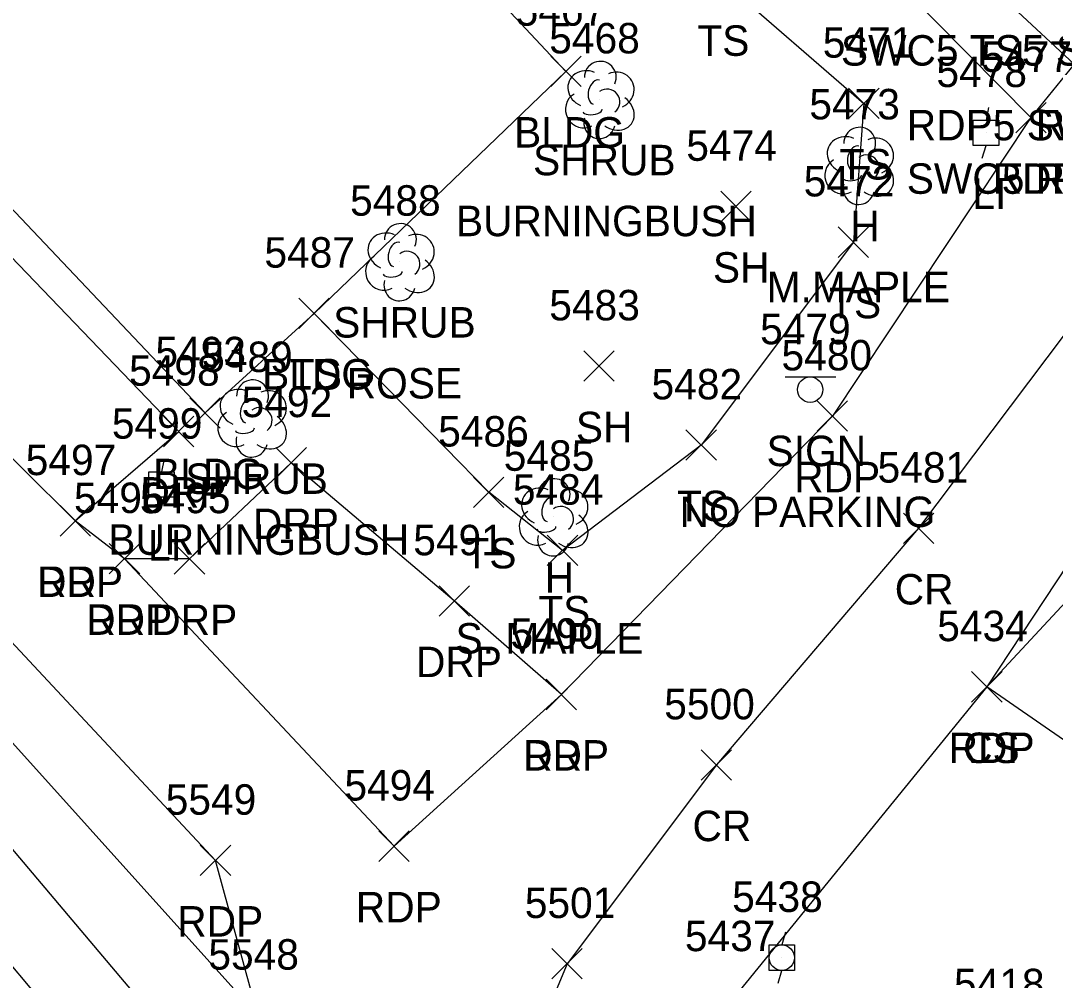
# Model space of a CAD drawing. Extents: x 1618146 to 1620418, y 640749 to 641927.
# Drawn here: x 1620177.9 to 1620245.8, y 641136.7 to 641199.7 of the extents above; entities that cross this region are included whole.
import ezdxf

# ---------------------------------------------------------------- set-up
doc = ezdxf.new("R2010")
doc.units = 0
for name, color, linetype in [('L_A', 7, 'Continuous'), ('L_C', 7, 'Continuous'), ('L_I', 7, 'Continuous'), ('L_TIC', 7, 'Continuous'), ('LBC', 7, 'Continuous'), ('LELB', 7, 'Continuous'), ('LSH', 7, 'Continuous'), ('LTD', 7, 'Continuous'), ('P_A', 7, 'Continuous'), ('P_I', 7, 'Continuous'), ('P_TIC', 7, 'Continuous'), ('PET', 7, 'Continuous'), ('PRC', 7, 'Continuous'), ('R_A', 7, 'Continuous'), ('R_I', 7, 'Continuous'), ('R_TIC', 7, 'Continuous'), ('RDP', 7, 'Continuous'), ('RR', 7, 'Continuous'), ('RRB', 7, 'Continuous'), ('RSW', 7, 'Continuous'), ('S_A', 7, 'Continuous'), ('S_C', 7, 'Continuous'), ('S_I', 7, 'Continuous'), ('SSGN', 7, 'Continuous'), ('U_A', 7, 'Continuous'), ('U_I', 7, 'Continuous'), ('ULP', 7, 'Continuous'), ('UP', 7, 'Continuous')]:
    doc.layers.add(name, color=color, linetype=linetype)

msp = doc.modelspace()

# ---------------------------------------------------------------- linework, layer by layer
at = {"layer": 'L_TIC'}
for points in [[(1620212.685, 641195.392), (1620214.685, 641197.392)], [(1620214.685, 641195.392), (1620212.685, 641197.392)], [(1620232.244, 641193.294), (1620234.244, 641195.294)], [(1620234.244, 641193.294), (1620232.244, 641195.294)], [(1620223.848, 641186.523), (1620225.848, 641188.523)], [(1620225.848, 641186.523), (1620223.848, 641188.523)], [(1620231.558, 641184.185), (1620233.558, 641186.185)], [(1620233.558, 641184.185), (1620231.558, 641186.185)], [(1620196.139, 641179.509), (1620198.139, 641181.509)], [(1620198.139, 641179.509), (1620196.139, 641181.509)], [(1620196.139, 641179.509), (1620198.139, 641181.509)], [(1620198.139, 641179.509), (1620196.139, 641181.509)], [(1620214.849, 641176.047), (1620216.849, 641178.047)], [(1620216.849, 641176.047), (1620214.849, 641178.047)], [(1620188.981, 641172.967), (1620190.981, 641174.967)], [(1620190.981, 641172.967), (1620188.981, 641174.967)], [(1620221.564, 641170.861), (1620223.564, 641172.861)], [(1620223.564, 641170.861), (1620221.564, 641172.861)], [(1620207.609, 641167.764), (1620209.609, 641169.764)], [(1620209.609, 641167.764), (1620207.609, 641169.764)], [(1620212.458, 641163.948), (1620214.458, 641165.948)], [(1620214.458, 641163.948), (1620212.458, 641165.948)], [(1620240.328, 641154.987), (1620242.328, 641156.987)], [(1620242.328, 641154.987), (1620240.328, 641156.987)], [(1620240.328, 641154.987), (1620242.328, 641156.987)], [(1620242.328, 641154.987), (1620240.328, 641156.987)]]:
    msp.add_lwpolyline(points, dxfattribs=at)
at = {"layer": 'LBC'}
msp.add_lwpolyline([(1620215.058, 641244.302), (1620205.976, 641235.712), (1620202.677, 641232.585), (1620189.499, 641220.107), (1620199.083, 641211.828), (1620201.415, 641213.808), (1620202.472, 641212.521), (1620205.827, 641209.331), (1620206.941, 641208.229), (1620204.756, 641205.896), (1620213.685, 641196.392), (1620197.139, 641180.509), (1620189.981, 641173.967), (1620166.556, 641198.685), (1620162.715, 641202.828), (1620152.839, 641213.225), (1620141.669, 641224.901), (1620165.022, 641247.378), (1620169.209, 641243.063), (1620193.587, 641266.433)], dxfattribs=at)
at = {"layer": 'LELB'}
for points in [[(1620211.815, 641214.968), (1620223.903, 641202.414), (1620233.244, 641194.294), (1620232.558, 641185.185), (1620222.564, 641171.861), (1620213.458, 641164.948), (1620208.609, 641168.764), (1620197.139, 641180.509)], [(1620322.254, 641104.578), (1620328.726, 641115.395), (1620332.253, 641122.244), (1620297.17, 641147.26), (1620261.974, 641167.003), (1620254.964, 641172.982), (1620251.385, 641166.829), (1620241.328, 641155.987)], [(1620310.491, 641089.313), (1620322.254, 641104.578), (1620287.408, 641125.429), (1620251.671, 641148.83), (1620241.328, 641155.987)]]:
    msp.add_lwpolyline(points, dxfattribs=at)
at = {"layer": 'LSH'}
for p, q in [((1620215.893, 641194.573), (1620215.893, 641194.573)), ((1620215.893, 641194.573), (1620215.893, 641194.573)), ((1620202.766, 641183.919), (1620202.766, 641183.919)), ((1620202.766, 641183.919), (1620202.766, 641183.919)), ((1620193.057, 641173.656), (1620193.057, 641173.656)), ((1620193.057, 641173.656), (1620193.057, 641173.656))]:
    msp.add_line(p, q, dxfattribs=at)
for centre in [(1620215.94, 641196.007), (1620202.813, 641185.353), (1620193.104, 641175.09)]:
    msp.add_arc(centre, 1.047, 335.52715, 180.95627, dxfattribs=at)
for centre, major_axis, ratio, start_param, end_param in [((1620215.101, 641195.24), (1.21, -0.512), 0.895232, 1.570796, 4.712389), ((1620216.935, 641195.157), (-1.141, -0.483), 0.949671, 1.570796, 4.712389), ((1620215.685, 641195.032), (-0.208, -0.792), 0.645439, 3.141593, 6.283185), ((1620216.393, 641194.407), (-0.5, 0.667), 0.989748, 3.141593, 6.283185), ((1620214.81, 641193.865), (0.584, -1.042), 0.959034, 3.141593, 6.283185), ((1620216.893, 641193.74), (-1.09, 0.792), 0.841452, 1.570796, 4.712389), ((1620215.435, 641193.823), (-0.625, -0.083), 0.423636, 0, 3.141593), ((1620215.893, 641193.073), (0.265, 1.061), 0.942809, 1.570796, 4.712389), ((1620201.974, 641184.586), (1.21, -0.512), 0.895232, 1.570796, 4.712389), ((1620203.807, 641184.503), (-1.141, -0.483), 0.949671, 1.570796, 4.712389), ((1620202.557, 641184.377), (-0.208, -0.792), 0.645439, 3.141593, 6.283185), ((1620201.683, 641183.211), (0.584, -1.042), 0.959034, 3.141593, 6.283185), ((1620203.266, 641183.752), (-0.5, 0.667), 0.989748, 3.141593, 6.283185), ((1620203.766, 641183.086), (-1.09, 0.792), 0.841452, 1.570796, 4.712389), ((1620202.308, 641183.169), (-0.625, -0.083), 0.423636, 0, 3.141593), ((1620202.766, 641182.419), (0.265, 1.061), 0.942809, 1.570796, 4.712389), ((1620192.265, 641174.323), (1.21, -0.512), 0.895232, 1.570796, 4.712389), ((1620194.098, 641174.24), (-1.141, -0.483), 0.949671, 1.570796, 4.712389), ((1620192.848, 641174.114), (-0.208, -0.792), 0.645439, 3.141593, 6.283185), ((1620193.557, 641173.489), (-0.5, 0.667), 0.989748, 3.141593, 6.283185), ((1620191.974, 641172.947), (0.584, -1.042), 0.959034, 3.141593, 6.283185), ((1620194.057, 641172.823), (-1.09, 0.792), 0.841452, 1.570796, 4.712389), ((1620192.599, 641172.906), (-0.625, -0.083), 0.423636, 0, 3.141593), ((1620193.057, 641172.156), (0.265, 1.061), 0.942809, 1.570796, 4.712389)]:
    msp.add_ellipse(centre, major_axis=major_axis, ratio=ratio, start_param=start_param, end_param=end_param, dxfattribs=at)
at = {"layer": 'LTD'}
for p, q in [((1620232.926, 641190.242), (1620232.926, 641190.242)), ((1620232.926, 641190.242), (1620232.926, 641190.242)), ((1620212.857, 641167.173), (1620212.857, 641167.173)), ((1620212.857, 641167.173), (1620212.857, 641167.173))]:
    msp.add_line(p, q, dxfattribs=at)
for centre in [(1620232.973, 641191.676), (1620212.904, 641168.607)]:
    msp.add_arc(centre, 1.047, 335.52715, 180.95627, dxfattribs=at)
for centre, major_axis, ratio, start_param, end_param in [((1620232.135, 641190.909), (1.21, -0.512), 0.895232, 1.570796, 4.712389), ((1620233.968, 641190.826), (-1.141, -0.483), 0.949671, 1.570796, 4.712389), ((1620232.718, 641190.7), (-0.208, -0.792), 0.645439, 3.141593, 6.283185), ((1620231.843, 641189.534), (0.584, -1.042), 0.959034, 3.141593, 6.283185), ((1620233.426, 641190.076), (-0.5, 0.667), 0.989748, 3.141593, 6.283185), ((1620233.927, 641189.409), (-1.09, 0.792), 0.841452, 1.570796, 4.712389), ((1620232.468, 641189.492), (-0.625, -0.083), 0.423636, 0, 3.141593), ((1620232.927, 641188.742), (0.265, 1.061), 0.942809, 1.570796, 4.712389), ((1620212.065, 641167.839), (1.21, -0.512), 0.895232, 1.570796, 4.712389), ((1620213.899, 641167.756), (-1.141, -0.483), 0.949671, 1.570796, 4.712389), ((1620212.649, 641167.631), (-0.208, -0.792), 0.645439, 3.141593, 6.283185), ((1620213.357, 641167.006), (-0.5, 0.667), 0.989748, 3.141593, 6.283185), ((1620211.774, 641166.464), (0.584, -1.042), 0.959034, 3.141593, 6.283185), ((1620213.857, 641166.34), (-1.09, 0.792), 0.841452, 1.570796, 4.712389), ((1620212.857, 641165.673), (0.265, 1.061), 0.942809, 1.570796, 4.712389), ((1620212.399, 641166.423), (-0.625, -0.083), 0.423636, 0, 3.141593)]:
    msp.add_ellipse(centre, major_axis=major_axis, ratio=ratio, start_param=start_param, end_param=end_param, dxfattribs=at)
at = {"layer": 'P_TIC'}
for points in [[(1620243.221, 641192.357), (1620245.221, 641194.357)], [(1620245.221, 641192.357), (1620243.221, 641194.357)], [(1620230.184, 641172.763), (1620232.184, 641174.763)], [(1620232.184, 641172.763), (1620230.184, 641174.763)], [(1620180.462, 641165.888), (1620182.462, 641167.888)], [(1620182.462, 641165.888), (1620180.462, 641167.888)], [(1620235.843, 641165.396), (1620237.843, 641167.396)], [(1620237.843, 641165.396), (1620235.843, 641167.396)], [(1620183.689, 641163.4), (1620185.689, 641165.4)], [(1620185.689, 641163.4), (1620183.689, 641165.4)], [(1620212.381, 641154.488), (1620214.381, 641156.488)], [(1620214.381, 641154.488), (1620212.381, 641156.488)], [(1620240.328, 641154.987), (1620242.328, 641156.987)], [(1620242.328, 641154.987), (1620240.328, 641156.987)], [(1620222.563, 641149.858), (1620224.563, 641151.858)], [(1620224.563, 641149.858), (1620222.563, 641151.858)], [(1620201.395, 641144.525), (1620203.395, 641146.525)], [(1620203.395, 641144.525), (1620201.395, 641146.525)], [(1620189.666, 641143.593), (1620191.666, 641145.593)], [(1620191.666, 641143.593), (1620189.666, 641145.593)], [(1620212.753, 641136.811), (1620214.753, 641138.811)], [(1620214.753, 641136.811), (1620212.753, 641138.811)]]:
    msp.add_lwpolyline(points, dxfattribs=at)
at = {"layer": 'PET'}
for points in [[(1620248.37, 641210.419), (1620247.05, 641196.867), (1620244.221, 641193.357), (1620231.184, 641173.763), (1620213.381, 641155.488), (1620202.395, 641145.525), (1620184.689, 641164.4), (1620181.462, 641166.888), (1620163.819, 641184.387), (1620152.297, 641193.8)], [(1620264.261, 641193.837), (1620257.522, 641181.671), (1620253.5, 641174.421), (1620241.328, 641155.987), (1620224.756, 641135.636), (1620223.78, 641130.066), (1620229.044, 641107.516), (1620237.42, 641090.889)], [(1620199.84, 641100.892), (1620190.476, 641119.747), (1620190.752, 641121.585), (1620192.149, 641127.788), (1620193.459, 641134.423), (1620190.666, 641144.593), (1620174.447, 641161.945), (1620160.08, 641178.417), (1620147.247, 641189.39)]]:
    msp.add_lwpolyline(points, dxfattribs=at)
at = {"layer": 'PRC'}
msp.add_lwpolyline([(1620256.843, 641199.417), (1620250.092, 641183.972), (1620236.843, 641166.396), (1620223.563, 641150.858), (1620213.753, 641137.811), (1620205.802, 641118.707)], dxfattribs=at)
at = {"layer": 'R_TIC'}
for points in [[(1620243.221, 641192.357), (1620245.221, 641194.357)], [(1620245.221, 641192.357), (1620243.221, 641194.357)], [(1620187.251, 641171.756), (1620189.251, 641173.756)], [(1620189.251, 641171.756), (1620187.251, 641173.756)], [(1620194.641, 641169.695), (1620196.641, 641171.695)], [(1620196.641, 641169.695), (1620194.641, 641171.695)], [(1620180.462, 641165.888), (1620182.462, 641167.888)], [(1620182.462, 641165.888), (1620180.462, 641167.888)], [(1620183.689, 641163.4), (1620185.689, 641165.4)], [(1620185.689, 641163.4), (1620183.689, 641165.4)], [(1620187.963, 641163.388), (1620189.963, 641165.388)], [(1620189.963, 641163.388), (1620187.963, 641165.388)], [(1620205.348, 641160.625), (1620207.348, 641162.625)], [(1620207.348, 641160.625), (1620205.348, 641162.625)], [(1620212.381, 641154.488), (1620214.381, 641156.488)], [(1620214.381, 641154.488), (1620212.381, 641156.488)]]:
    msp.add_lwpolyline(points, dxfattribs=at)
at = {"layer": 'RDP'}
for points in [[(1620181.462, 641166.888), (1620188.251, 641172.756), (1620165.106, 641196.848), (1620161.474, 641200.94), (1620159.631, 641200.696)], [(1620213.381, 641155.488), (1620206.348, 641161.625), (1620195.641, 641170.695), (1620188.963, 641164.388), (1620184.689, 641164.4)]]:
    msp.add_lwpolyline(points, dxfattribs=at)
at = {"layer": 'RR'}
for points in [[(1620192.149, 641127.788), (1620168.312, 641155.994), (1620153.359, 641171.838), (1620133.437, 641191.994), (1620110.111, 641213.081), (1620101.472, 641220.641), (1620055.356, 641258.678), (1620021.942, 641286.099), (1619984.199, 641317.184), (1619946.809, 641347.804), (1619927.299, 641363.881), (1619890.892, 641393.618), (1619862.546, 641416.891)], [(1620190.752, 641121.585), (1620164.758, 641152.663), (1620149.827, 641168.387), (1620129.761, 641188.505), (1620106.878, 641209.401), (1620098.404, 641216.876), (1620053.4, 641253.963), (1620018.83, 641282.236), (1619980.557, 641313.635), (1619944.224, 641343.671), (1619924.209, 641360.052), (1619888.22, 641389.605), (1619859.159, 641413.425)]]:
    msp.add_lwpolyline(points, dxfattribs=at)
at = {"layer": 'RRB'}
msp.add_lwpolyline([(1620282.833, 641005.905), (1620262.956, 641036.105), (1620245.554, 641062.879), (1620222.8, 641095.958), (1620205.802, 641118.707), (1620193.459, 641134.423), (1620171.398, 641158.878), (1620156.473, 641175.88), (1620136.028, 641194.899), (1620112.946, 641215.974), (1620104.578, 641223.126), (1620095.968, 641212.166)], dxfattribs=at)
at = {"layer": 'RSW'}
for points in [[(1620247.05, 641196.867), (1620241.813, 641201.772), (1620221.011, 641223.739), (1620217.686, 641227.233), (1620214.968, 641229.37), (1620205.976, 641235.712)], [(1620202.677, 641232.585), (1620214.484, 641224.007), (1620217.542, 641220.644), (1620231.667, 641206.068), (1620244.221, 641193.357)]]:
    msp.add_lwpolyline(points, dxfattribs=at)
at = {"layer": 'SSGN'}
for p, q in [((1620228.075, 641176.332), (1620231.408, 641176.332)), ((1620229.722, 641175.499), (1620229.722, 641175.499))]:
    msp.add_line(p, q, dxfattribs=at)
msp.add_circle((1620229.722, 641175.499), 0.833, dxfattribs=at)
at = {"layer": 'ULP'}
for p, q in [((1620241.438, 641194.03), (1620241.272, 641193.197)), ((1620240.438, 641191.53), (1620240.438, 641193.197)), ((1620240.438, 641193.197), (1620242.105, 641193.197)), ((1620242.105, 641193.197), (1620242.105, 641191.53)), ((1620241.272, 641192.364), (1620241.272, 641192.364)), ((1620242.105, 641191.53), (1620240.438, 641191.53)), ((1620241.022, 641190.697), (1620241.272, 641191.53)), ((1620187.298, 641170.948), (1620187.131, 641170.114)), ((1620186.298, 641168.448), (1620186.298, 641170.114)), ((1620186.298, 641170.114), (1620187.964, 641170.114)), ((1620187.964, 641170.114), (1620187.964, 641168.448)), ((1620187.131, 641169.281), (1620187.131, 641169.281)), ((1620187.964, 641168.448), (1620186.298, 641168.448)), ((1620186.881, 641167.614), (1620187.131, 641168.448))]:
    msp.add_line(p, q, dxfattribs=at)
at = {"layer": 'UP'}
for p, q in [((1620228.11, 641139.876), (1620227.86, 641139.043)), ((1620227.027, 641137.376), (1620227.027, 641139.043)), ((1620227.027, 641139.043), (1620228.693, 641139.043)), ((1620228.693, 641139.043), (1620228.693, 641137.376)), ((1620227.86, 641138.21), (1620227.86, 641138.21)), ((1620228.693, 641137.376), (1620227.027, 641137.376)), ((1620227.61, 641136.543), (1620227.86, 641137.376))]:
    msp.add_line(p, q, dxfattribs=at)
msp.add_circle((1620227.86, 641138.21), 0.833, dxfattribs=at)

# ---------------------------------------------------------------- texts
at = {"layer": 'L_A'}
for s, p in [('TS', (1620222.313, 641197.414)), ('TS', (1620240.222, 641196.772)), ('BLDG', (1620210.276, 641191.392)), ('SHRUB', (1620211.523, 641189.573)), ('TS', (1620231.654, 641189.294)), ('H', (1620232.359, 641185.242)), ('SH', (1620223.336, 641182.523)), ('TS', (1620230.968, 641180.185)), ('SHRUB', (1620198.396, 641178.919)), ('BLDG', (1620193.73, 641175.509)), ('TS', (1620195.549, 641175.509)), ('SH', (1620214.337, 641172.047)), ('BLDG', (1620186.572, 641168.967)), ('SHRUB', (1620188.687, 641168.656)), ('TS', (1620220.974, 641166.861)), ('TS', (1620207.018, 641163.764)), ('H', (1620212.29, 641162.173)), ('TS', (1620211.868, 641159.948)), ('CS', (1620239.769, 641150.987)), ('CS', (1620239.769, 641150.987))]:
    msp.add_text(s, height=2, dxfattribs=at).set_placement(p)
at = {"layer": 'L_C'}
for s, p in [('BURNINGBUSH', (1620206.46, 641185.573)), ('M.MAPLE', (1620226.864, 641181.242)), ('ROSE', (1620199.286, 641174.919)), ('BURNINGBUSH', (1620183.624, 641164.656)), ('S. MAPLE', (1620206.432, 641158.173))]:
    msp.add_text(s, height=2, dxfattribs=at).set_placement(p)
at = {"layer": 'L_I'}
for s, p in [('5467', (1620210.378, 641199.392)), ('5468', (1620212.586, 641197.573)), ('5471', (1620230.551, 641197.294)), ('5473', (1620229.667, 641193.242)), ('5474', (1620221.588, 641190.523)), ('5472', (1620229.298, 641188.185)), ('5488', (1620199.506, 641186.919)), ('5487', (1620193.879, 641183.509)), ('5487', (1620193.879, 641183.509)), ('5483', (1620212.589, 641180.047)), ('5493', (1620186.722, 641176.967)), ('5489', (1620189.789, 641176.656)), ('5482', (1620219.304, 641174.861)), ('5486', (1620205.294, 641171.764)), ('5485', (1620209.597, 641170.173)), ('5484', (1620210.198, 641167.948)), ('5434', (1620238.068, 641158.987)), ('5434', (1620238.068, 641158.987)), ('5437', (1620221.496, 641138.636)), ('5418', (1620239.167, 641135.48))]:
    msp.add_text(s, height=2, dxfattribs=at).set_placement(p)
at = {"layer": 'P_A'}
for s, p in [('RDP', (1620244.538, 641191.867)), ('RDP', (1620241.709, 641188.357)), ('RDP', (1620228.672, 641168.763)), ('RDP', (1620178.95, 641161.888)), ('CR', (1620235.276, 641161.396)), ('RDP', (1620182.178, 641159.4)), ('RDP', (1620210.869, 641150.488)), ('RDP', (1620238.816, 641150.987)), ('CR', (1620221.996, 641145.858)), ('RDP', (1620199.883, 641140.525)), ('RDP', (1620188.154, 641139.593))]:
    msp.add_text(s, height=2, dxfattribs=at).set_placement(p)
at = {"layer": 'P_I'}
for s, p in [('5477', (1620240.962, 641196.357)), ('5480', (1620227.838, 641176.763)), ('5497', (1620178.202, 641169.888)), ('5481', (1620234.15, 641169.396)), ('5496', (1620181.374, 641167.4)), ('5490', (1620210.035, 641158.488)), ('5434', (1620238.068, 641158.987)), ('5500', (1620220.138, 641153.858)), ('5494', (1620199.135, 641148.525)), ('5549', (1620187.398, 641147.593)), ('5501', (1620210.981, 641140.811)), ('5437', (1620221.496, 641138.636)), ('5548', (1620190.199, 641137.423))]:
    msp.add_text(s, height=2, dxfattribs=at).set_placement(p)
at = {"layer": 'R_A'}
for s, p in [('SWC5 TS5 ST', (1620231.742, 641196.772)), ('RDP5 SWC5 ST', (1620236.066, 641191.867)), ('SWC5 RDP5', (1620236.064, 641188.357)), ('DRP', (1620185.74, 641167.756)), ('DRP', (1620193.13, 641165.695)), ('DRP', (1620178.95, 641161.888)), ('DRP', (1620182.178, 641159.4)), ('DRP', (1620186.451, 641159.388)), ('DRP', (1620203.837, 641156.625)), ('DRP', (1620210.869, 641150.488))]:
    msp.add_text(s, height=2, dxfattribs=at).set_placement(p)
at = {"layer": 'R_I'}
for s, p in [('5477', (1620240.962, 641196.357)), ('5498', (1620184.992, 641175.756)), ('5492', (1620192.382, 641173.695)), ('5497', (1620178.202, 641169.888)), ('5496', (1620181.374, 641167.4)), ('5495', (1620185.703, 641167.388)), ('5491', (1620203.656, 641164.625)), ('5490', (1620210.035, 641158.488)), ('5548', (1620190.199, 641137.423))]:
    msp.add_text(s, height=2, dxfattribs=at).set_placement(p)
at = {"layer": 'S_A'}
msp.add_text('SIGN', height=2, dxfattribs=at).set_placement((1620226.86, 641170.478))
at = {"layer": 'S_C'}
msp.add_text('NO PARKING', height=2, dxfattribs=at).set_placement((1620221.143, 641166.478))
at = {"layer": 'S_I'}
msp.add_text('5479', height=2, dxfattribs=at).set_placement((1620226.434, 641178.478))
at = {"layer": 'U_A'}
for p in [(1620240.374, 641187.364), (1620186.233, 641164.281)]:
    msp.add_text('LI', height=2, dxfattribs=at).set_placement(p)
at = {"layer": 'U_I'}
for s, p in [('5478', (1620238.012, 641195.364)), ('5499', (1620183.863, 641172.281)), ('5438', (1620224.6, 641141.21))]:
    msp.add_text(s, height=2, dxfattribs=at).set_placement(p)

doc.saveas('drawing.dxf')
